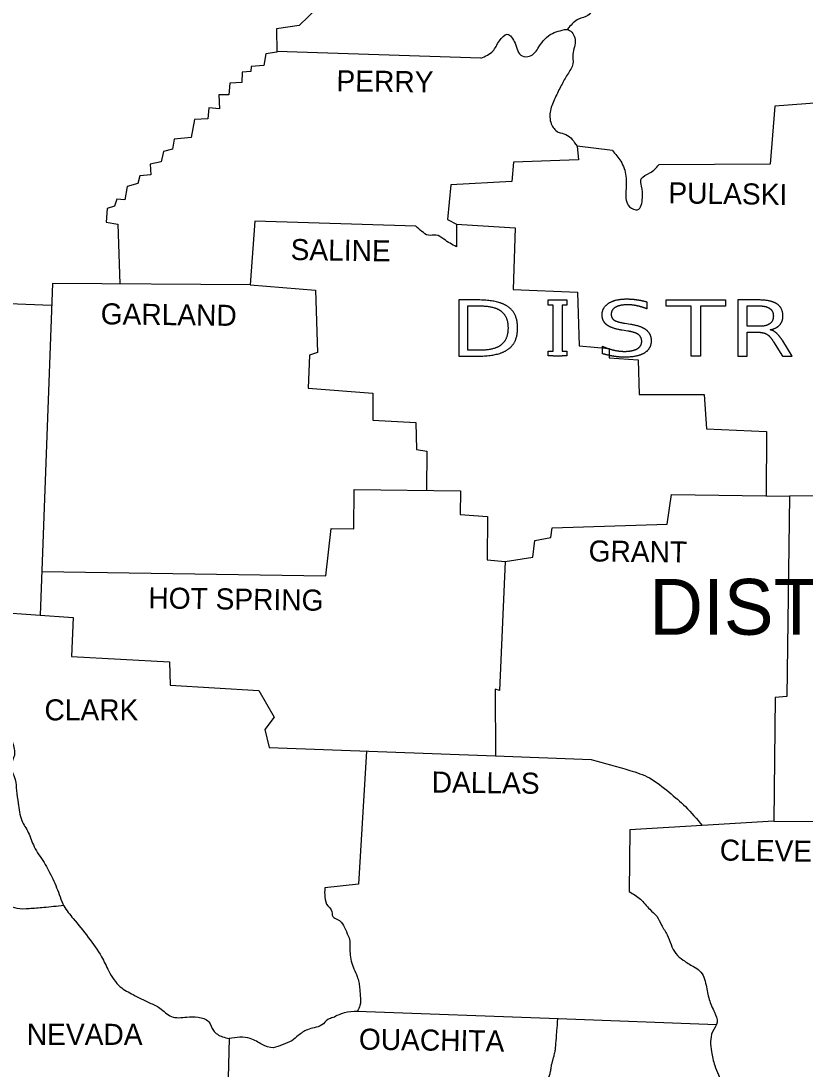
# Model space of a CAD drawing. Extents: x -0.96 to 2.36, y -0.12 to 0.92.
# Drawn here: x 1.1608 to 1.2333, y 0.624 to 0.7208 of the extents above; entities that cross this region are included whole.
import ezdxf

# ---------------------------------------------------------------- set-up
doc = ezdxf.new("R2010")
doc.units = 0
doc.layers.add('SHET_Annotations', color=7, linetype='Continuous')

msp = doc.modelspace()

# ---------------------------------------------------------------- linework, layer by layer
at = {"layer": 'SHET_Annotations'}
for p, q in [((1.211496, 0.720197), (1.211336, 0.720023)), ((1.218708, 0.694862), (1.218708, 0.694215)), ((1.216665, 0.692883), (1.217197, 0.692796)), ((1.216948, 0.692159), (1.216412, 0.692243)), ((1.230111, 0.692278), (1.230111, 0.692278)), ((1.214591, 0.690068), (1.214591, 0.690754))]:
    msp.add_line(p, q, dxfattribs=at)
for points in [[(1.233615, 0.817917), (1.233721, 0.806791), (1.232969, 0.806739), (1.233073, 0.79538), (1.229909, 0.794913), (1.230168, 0.791879), (1.231257, 0.790452), (1.23118, 0.786847), (1.224981, 0.786614), (1.224748, 0.781064), (1.219094, 0.780883), (1.218783, 0.774088), (1.21912, 0.773569), (1.219276, 0.76278), (1.229001, 0.762132), (1.228871, 0.738091), (1.236652, 0.737884), (1.236652, 0.713402), (1.230531, 0.712935), (1.23009, 0.707592), (1.219795, 0.707515)], [(1.18831, 0.72209), (1.186547, 0.720404), (1.184472, 0.720067), (1.184498, 0.717914), (1.183487, 0.717785), (1.183305, 0.716695), (1.182138, 0.716592), (1.182086, 0.716125), (1.181282, 0.716073), (1.181256, 0.715113), (1.180141, 0.715062), (1.180063, 0.713972), (1.17913, 0.713972), (1.179182, 0.712676), (1.178196, 0.712779), (1.178118, 0.711768), (1.176899, 0.71169), (1.176562, 0.71003), (1.175006, 0.709901), (1.174851, 0.708967), (1.174021, 0.70876), (1.173813, 0.7078), (1.172776, 0.707592), (1.172854, 0.706607), (1.171816, 0.706503), (1.171635, 0.705777), (1.170675, 0.705518), (1.170442, 0.704273), (1.16969, 0.704351), (1.169482, 0.703702), (1.168808, 0.703469), (1.16873, 0.702224), (1.169793, 0.702043), (1.169983, 0.696509)], [(1.203352, 0.71737), (1.184497, 0.717994)], [(1.215515, 0.708837), (1.212248, 0.709226), (1.212377, 0.707981), (1.206387, 0.707748), (1.206205, 0.705985), (1.200577, 0.705673), (1.200266, 0.702458), (1.201096, 0.702043), (1.201096, 0.699942)], [(1.197335, 0.701861), (1.182449, 0.702302), (1.182034, 0.696441), (1.163751, 0.696545), (1.162627, 0.665923)], [(1.201096, 0.702037), (1.206542, 0.701705), (1.206335, 0.696), (1.2123, 0.695766), (1.212429, 0.690787), (1.21523, 0.690554), (1.21523, 0.689698), (1.217901, 0.68949), (1.217979, 0.686301), (1.223996, 0.686301), (1.224203, 0.683137), (1.229753, 0.682877), (1.229727, 0.676943)], [(1.182034, 0.696441), (1.188077, 0.695922), (1.188259, 0.690165), (1.187506, 0.689931), (1.187403, 0.686871), (1.193368, 0.68643), (1.193368, 0.683915), (1.197335, 0.683707), (1.197413, 0.681217), (1.198347, 0.681062), (1.198319, 0.677447)], [(1.145519, 0.695248), (1.163677, 0.694537)], [(1.203115, 0.69503), (1.201329, 0.69503), (1.201329, 0.689845), (1.203115, 0.689845)], [(1.20325, 0.69039), (1.202165, 0.69039), (1.202165, 0.694484), (1.20325, 0.694484)], [(1.229087, 0.69503), (1.227122, 0.69503), (1.227122, 0.689845), (1.227959, 0.689845), (1.227959, 0.692051), (1.228939, 0.692051)], [(1.229087, 0.692596), (1.227959, 0.692596), (1.227959, 0.694484), (1.229087, 0.694484)], [(1.230407, 0.691173), (1.231235, 0.689845), (1.232128, 0.689845), (1.231256, 0.691247)], [(1.284163, 0.682177), (1.266891, 0.68267), (1.266787, 0.677042), (1.23188, 0.676912)], [(1.162775, 0.669939), (1.189037, 0.669547), (1.189529, 0.673904), (1.191604, 0.673878), (1.191656, 0.677535), (1.201485, 0.677405), (1.201433, 0.675201), (1.203975, 0.675019), (1.203949, 0.671025), (1.205609, 0.67087)], [(1.205609, 0.67087), (1.20815, 0.671259), (1.208332, 0.672815), (1.209836, 0.673074), (1.20994, 0.673982), (1.220573, 0.674319), (1.220987, 0.677068), (1.23188, 0.676912)], [(1.23188, 0.676912), (1.231646, 0.658395), (1.230557, 0.658317), (1.230453, 0.646881)], [(1.205609, 0.67087), (1.205064, 0.65894), (1.204675, 0.65907), (1.204701, 0.65291)], [(1.157578, 0.657721), (1.157449, 0.660237), (1.158201, 0.660288), (1.158668, 0.666201), (1.16567, 0.665709), (1.165514, 0.662104), (1.174565, 0.661611), (1.174643, 0.659433), (1.182838, 0.65894), (1.184239, 0.656476), (1.183383, 0.655361), (1.183798, 0.653675), (1.204701, 0.65291)], [(1.192778, 0.653346), (1.192045, 0.641071), (1.188933, 0.640708)], [(1.204701, 0.65291), (1.213544, 0.652586)], [(1.230453, 0.646881), (1.223815, 0.64648)], [(1.230453, 0.646881), (1.246686, 0.646802)], [(1.223815, 0.64648), (1.217123, 0.646077), (1.217071, 0.640371)], [(1.191933, 0.629337), (1.21051, 0.628649), (1.22514, 0.628079)], [(1.180089, 0.626807), (1.179493, 0.603778), (1.173346, 0.604219), (1.173294, 0.602533), (1.165185, 0.603001)]]:
    msp.add_lwpolyline(points, dxfattribs=at)
for points in [[(1.210034, 0.69454), (1.209572, 0.69454), (1.209572, 0.695058), (1.211306, 0.695058), (1.211306, 0.69454), (1.21087, 0.69454), (1.21087, 0.690296), (1.211306, 0.690296), (1.211306, 0.689859), (1.21087, 0.689859), (1.21087, 0.689845), (1.210034, 0.689845), (1.210034, 0.689859), (1.209589, 0.689859), (1.209589, 0.690296), (1.210034, 0.690296)], [(1.2205, 0.69503), (1.225958, 0.69503), (1.225958, 0.69447), (1.223649, 0.69447), (1.223649, 0.689845), (1.222809, 0.689845), (1.222809, 0.69447), (1.2205, 0.69447)]]:
    msp.add_lwpolyline(points, close=True, dxfattribs=at)
for points in [[(1.215567, 0.732775), (1.214945, 0.731711), (1.214711, 0.730337), (1.213959, 0.729455), (1.213493, 0.728495), (1.213467, 0.727147), (1.213674, 0.725954), (1.213907, 0.724839), (1.214115, 0.723775), (1.213856, 0.722453), (1.213259, 0.721312), (1.212377, 0.720975), (1.211496, 0.720197)], [(1.203352, 0.71737), (1.204467, 0.718018), (1.205064, 0.718978), (1.20579, 0.719574), (1.206516, 0.718744), (1.207165, 0.717577), (1.207865, 0.717551), (1.208721, 0.718407), (1.209265, 0.719133), (1.209965, 0.719652), (1.210692, 0.719911), (1.211444, 0.719989), (1.212066, 0.719107), (1.211859, 0.717733), (1.211859, 0.716851), (1.211366, 0.715865), (1.210795, 0.714854), (1.210225, 0.713713), (1.209784, 0.71252), (1.209862, 0.711301), (1.21051, 0.710549), (1.21121, 0.710316), (1.212248, 0.709226)], [(1.215515, 0.708837), (1.216293, 0.707852), (1.21676, 0.706477), (1.21676, 0.704921), (1.217097, 0.70365), (1.217849, 0.703365), (1.21829, 0.70448), (1.218213, 0.705544), (1.218187, 0.706218), (1.218991, 0.706763), (1.219795, 0.707515)], [(1.201096, 0.699942), (1.199929, 0.700642), (1.199203, 0.701031), (1.198503, 0.701005), (1.197906, 0.701368), (1.197335, 0.701861)], [(1.157578, 0.657721), (1.158279, 0.65728), (1.15916, 0.656865), (1.159627, 0.656191), (1.159783, 0.655128), (1.16012, 0.653986), (1.160198, 0.652819), (1.159938, 0.652171), (1.160301, 0.650719), (1.160431, 0.649707), (1.160587, 0.64854), (1.160924, 0.646932), (1.16152, 0.645843), (1.162065, 0.64452), (1.162973, 0.643068), (1.163777, 0.641538), (1.16414, 0.640734), (1.164814, 0.639048), (1.16567, 0.637881), (1.16707, 0.636144), (1.168289, 0.634354), (1.168963, 0.633032), (1.170027, 0.631579), (1.17122, 0.630853), (1.172724, 0.630101), (1.173684, 0.629608), (1.174747, 0.62883), (1.176173, 0.628778), (1.177211, 0.628778), (1.178196, 0.628338), (1.178637, 0.627534), (1.179467, 0.626963), (1.180089, 0.626807)], [(1.213544, 0.652586), (1.217123, 0.651575), (1.218939, 0.650874), (1.220754, 0.649552), (1.222258, 0.648229), (1.223815, 0.64648)], [(1.138889, 0.642596), (1.140799, 0.642446), (1.142407, 0.642264), (1.143626, 0.642135), (1.144897, 0.641694), (1.146064, 0.641279), (1.14679, 0.640942), (1.148009, 0.641019), (1.149072, 0.640812), (1.150239, 0.640397), (1.151121, 0.639619), (1.151691, 0.639022), (1.152729, 0.638789), (1.15361, 0.638945), (1.154648, 0.638841), (1.155815, 0.638504), (1.1568, 0.63853), (1.157578, 0.638711), (1.158486, 0.638919), (1.159601, 0.639048), (1.160457, 0.638841), (1.161598, 0.638815), (1.162947, 0.638919), (1.164777, 0.639118)], [(1.188933, 0.640708), (1.188933, 0.639852), (1.189218, 0.639048), (1.189529, 0.638685), (1.189685, 0.638063), (1.1901, 0.637804), (1.19067, 0.637233), (1.191008, 0.636481), (1.191215, 0.635962), (1.191241, 0.635314), (1.191267, 0.634691), (1.191371, 0.633939), (1.191915, 0.632539), (1.192071, 0.631994), (1.192149, 0.631527), (1.192201, 0.630749), (1.192175, 0.629842), (1.191933, 0.629337)], [(1.217071, 0.640371), (1.218109, 0.639671), (1.218965, 0.638737), (1.219613, 0.638089), (1.220054, 0.637285), (1.220573, 0.636377), (1.221377, 0.63464), (1.222051, 0.634043), (1.22301, 0.633447), (1.223581, 0.633058), (1.224177, 0.631735), (1.224463, 0.630412), (1.224955, 0.629219), (1.225189, 0.628312), (1.224774, 0.627404), (1.22467, 0.625589), (1.224981, 0.624318), (1.225319, 0.623436), (1.225552, 0.622373), (1.225396, 0.622061)], [(1.189684, 0.628753), (1.189218, 0.628545), (1.188648, 0.628052), (1.187947, 0.627793), (1.187325, 0.627611), (1.186469, 0.627067), (1.185873, 0.6266), (1.184991, 0.626211), (1.184161, 0.625952), (1.183149, 0.626237), (1.182605, 0.626548), (1.182034, 0.626807), (1.180089, 0.626807)], [(1.189684, 0.628753), (1.190748, 0.629193), (1.191933, 0.629337)]]:
    msp.add_spline(points, degree=3, dxfattribs=at)
for points, degree in [([(1.205875, 0.694404), (1.204997, 0.69503), (1.203115, 0.69503)], 2), ([(1.20325, 0.694484), (1.204605, 0.694484), (1.205237, 0.693993)], 2), ([(1.206753, 0.692443), (1.206753, 0.693778), (1.205875, 0.694404)], 2), ([(1.214565, 0.693652), (1.214565, 0.694334), (1.215167, 0.694729)], 2), ([(1.215167, 0.694729), (1.215768, 0.695124), (1.216826, 0.695124)], 2), ([(1.215803, 0.694359), (1.215406, 0.694131), (1.215406, 0.693708)], 2), ([(1.216926, 0.694586), (1.216199, 0.694586), (1.215803, 0.694359)], 2), ([(1.216826, 0.695124), (1.217284, 0.695124), (1.217756, 0.695058)], 2), ([(1.217789, 0.694491), (1.21734, 0.694586), (1.216926, 0.694586)], 2), ([(1.217756, 0.695058), (1.218229, 0.694991), (1.218708, 0.694862)], 2), ([(1.218708, 0.694215), (1.218238, 0.694397), (1.217789, 0.694491)], 2), ([(1.230736, 0.694659), (1.230193, 0.69503), (1.229087, 0.69503)], 2), ([(1.229087, 0.694484), (1.229732, 0.694484), (1.230063, 0.694247)], 2), ([(1.231278, 0.693544), (1.231278, 0.694289), (1.230736, 0.694659)], 2), ([(1.205237, 0.693993), (1.205868, 0.693502), (1.205868, 0.692443)], 2), ([(1.214999, 0.692729), (1.214565, 0.693061), (1.214565, 0.693652)], 2), ([(1.215406, 0.693708), (1.215406, 0.693352), (1.215672, 0.693173)], 2), ([(1.230063, 0.694247), (1.230394, 0.694009), (1.230394, 0.693544)], 2), ([(1.230394, 0.693544), (1.230394, 0.693079), (1.230063, 0.692838)], 2), ([(1.230997, 0.692738), (1.231278, 0.693058), (1.231278, 0.693544)], 2), ([(1.205868, 0.692443), (1.205868, 0.691376), (1.205237, 0.690883)], 2), ([(1.205873, 0.690472), (1.206753, 0.6911), (1.206753, 0.692443)], 2), ([(1.216412, 0.692243), (1.215432, 0.692397), (1.214999, 0.692729)], 2), ([(1.215672, 0.693173), (1.215938, 0.692995), (1.216665, 0.692883)], 2), ([(1.217197, 0.692796), (1.218177, 0.692649), (1.218639, 0.692273)], 2), ([(1.230063, 0.692838), (1.229732, 0.692596), (1.229087, 0.692596)], 2), ([(1.230111, 0.692278), (1.230716, 0.692418), (1.230997, 0.692738)], 2), ([(1.217926, 0.691829), (1.217628, 0.692051), (1.216948, 0.692159)], 2), ([(1.218225, 0.691215), (1.218225, 0.691607), (1.217926, 0.691829)], 2), ([(1.218639, 0.692273), (1.2191, 0.691897), (1.2191, 0.691268)], 2), ([(1.228939, 0.692051), (1.22947, 0.692051), (1.229777, 0.691878)], 2), ([(1.229777, 0.691878), (1.230085, 0.691705), (1.230407, 0.691173)], 2), ([(1.230721, 0.691934), (1.230455, 0.692184), (1.230111, 0.692278)], 2), ([(1.231256, 0.691247), (1.230986, 0.691684), (1.230721, 0.691934)], 2), ([(1.203115, 0.689845), (1.204993, 0.689845), (1.205873, 0.690472)], 2), ([(1.205237, 0.690883), (1.204605, 0.69039), (1.20325, 0.69039)], 2), ([(1.214591, 0.690754), (1.215097, 0.69053), (1.215613, 0.690406)], 2), ([(1.215613, 0.690406), (1.216129, 0.690282), (1.21663, 0.690282)], 2), ([(1.21663, 0.690282), (1.217393, 0.690282), (1.217809, 0.690523)], 2), ([(1.217809, 0.690523), (1.218225, 0.690764), (1.218225, 0.691215)], 2), ([(1.2191, 0.691268), (1.2191, 0.690516), (1.218473, 0.69013)], 2), ([(1.215652, 0.689827), (1.215136, 0.689911), (1.214591, 0.690068)], 2), ([(1.21663, 0.689743), (1.216169, 0.689743), (1.215652, 0.689827)], 2), ([(1.218473, 0.69013), (1.217846, 0.689743), (1.21663, 0.689743)], 2), ([(1.210448, 0.628651), (1.210373, 0.627717), (1.210299, 0.626782), (1.210225, 0.625848), (1.210206, 0.625609), (1.210149, 0.625374), (1.210084, 0.625143), (1.210052, 0.625027), (1.210015, 0.624912), (1.209982, 0.624796), (1.20995, 0.62468), (1.209916, 0.624564), (1.209888, 0.624447), (1.209835, 0.624231), (1.20982, 0.624007), (1.209778, 0.623788), (1.209757, 0.623679), (1.209735, 0.62357), (1.209706, 0.623462), (1.209691, 0.623408), (1.209672, 0.623356), (1.20965, 0.623304), (1.20964, 0.623278), (1.209628, 0.623252), (1.209616, 0.623227), (1.209604, 0.623201), (1.209591, 0.623176), (1.209576, 0.623151), (1.209534, 0.623076), (1.209485, 0.623007), (1.209428, 0.622943), (1.209371, 0.62288), (1.209312, 0.622821), (1.20925, 0.622764), (1.209187, 0.622708), (1.209122, 0.622654), (1.20906, 0.622597), (1.208998, 0.622541), (1.208935, 0.622485), (1.208876, 0.622425), (1.208755, 0.622299), (1.208634, 0.622174), (1.208513, 0.622049), (1.208392, 0.621923), (1.208271, 0.621798), (1.20815, 0.621672), (1.207911, 0.621425), (1.207704, 0.621148), (1.207502, 0.620869), (1.207445, 0.62079), (1.207389, 0.62071), (1.207339, 0.620627), (1.20729, 0.620544), (1.20724, 0.62046), (1.20719, 0.620377), (1.207141, 0.620293), (1.207091, 0.620209), (1.207041, 0.620126), (1.206992, 0.620042), (1.206936, 0.619962), (1.206879, 0.619883), (1.206703, 0.619638), (1.206498, 0.619422), (1.206283, 0.619209), (1.20605, 0.618978), (1.205811, 0.618755), (1.205531, 0.618586), (1.205267, 0.618428), (1.204998, 0.618286), (1.204727, 0.618145), (1.204452, 0.618003), (1.204178, 0.617862), (1.203897, 0.61773), (1.20382, 0.617695), (1.203741, 0.617665), (1.203659, 0.617645), (1.203577, 0.617626), (1.203494, 0.617608), (1.203411, 0.617591), (1.203327, 0.617574), (1.203243, 0.617559), (1.203159, 0.617542), (1.203075, 0.617524), (1.202993, 0.617499), (1.202911, 0.617471), (1.202781, 0.617427), (1.202659, 0.617368), (1.202541, 0.617293), (1.202482, 0.617256), (1.202429, 0.617214), (1.202379, 0.617167), (1.202353, 0.617142), (1.202329, 0.617117), (1.202305, 0.617091), (1.20228, 0.617063), (1.202258, 0.617035), (1.202237, 0.617004), (1.20218, 0.616922), (1.202143, 0.616834), (1.202114, 0.616737), (1.202084, 0.616642), (1.202073, 0.616544), (1.202082, 0.616449), (1.2021, 0.61626), (1.202133, 0.616069), (1.202211, 0.615889), (1.202269, 0.615757), (1.202327, 0.615632), (1.202392, 0.615507), (1.202458, 0.615381), (1.202525, 0.615255), (1.202591, 0.615128), (1.202658, 0.615002), (1.202723, 0.614875), (1.202789, 0.614748), (1.202853, 0.614621), (1.20291, 0.614491), (1.202963, 0.614359), (1.203059, 0.61412), (1.203142, 0.613877), (1.203223, 0.613633), (1.203247, 0.613559), (1.203269, 0.613485), (1.20329, 0.61341), (1.203312, 0.613334), (1.203328, 0.613258), (1.203342, 0.61318), (1.203356, 0.613104), (1.203364, 0.613027), (1.203367, 0.61295), (1.203369, 0.612913), (1.203367, 0.612875), (1.203365, 0.612837), (1.203364, 0.612799), (1.203359, 0.612762), (1.203352, 0.612725), (1.203333, 0.612624), (1.203289, 0.612533), (1.203223, 0.612448), (1.203155, 0.61236), (1.203079, 0.612289), (1.202989, 0.612232), (1.202758, 0.612087), (1.202527, 0.611948), (1.202289, 0.611817), (1.201997, 0.611657), (1.201699, 0.611512), (1.201407, 0.611351), (1.201144, 0.611205), (1.200897, 0.61104), (1.200655, 0.610858), (1.200528, 0.610762), (1.200418, 0.61065), (1.200319, 0.610524), (1.20027, 0.610461), (1.200228, 0.610395), (1.200189, 0.610325), (1.200149, 0.610254), (1.200115, 0.610183), (1.200085, 0.610106), (1.200017, 0.609932), (1.199973, 0.609754), (1.199963, 0.609573), (1.199953, 0.609397), (1.199964, 0.609215), (1.200007, 0.609043), (1.200032, 0.60894), (1.200057, 0.608838), (1.200087, 0.608738), (1.200116, 0.608636), (1.200146, 0.608535), (1.200175, 0.608433), (1.200205, 0.608332), (1.200234, 0.60823), (1.200264, 0.608129), (1.200293, 0.608028), (1.20032, 0.607926), (1.200344, 0.607824), (1.200402, 0.607574), (1.200445, 0.607322), (1.200499, 0.607072), (1.200523, 0.606964), (1.200549, 0.606858), (1.200575, 0.606751), (1.200601, 0.606642), (1.200637, 0.606537), (1.200677, 0.606432), (1.200715, 0.606331), (1.20077, 0.60624), (1.200839, 0.606155), (1.200873, 0.606112), (1.200911, 0.606076), (1.200954, 0.606043), (1.200975, 0.606026), (1.200998, 0.606011), (1.201021, 0.605996), (1.201045, 0.605981), (1.201069, 0.605968), (1.201096, 0.605956), (1.201132, 0.605941), (1.201169, 0.605931), (1.201206, 0.605932), (1.201243, 0.605932), (1.20128, 0.605937), (1.201316, 0.605944), (1.201353, 0.605951), (1.201389, 0.605963), (1.201427, 0.605969), (1.201463, 0.605975), (1.2015, 0.605979), (1.201537, 0.605982), (1.201571, 0.605985), (1.201606, 0.605984), (1.201641, 0.605989), (1.201675, 0.605994), (1.20171, 0.606), (1.201744, 0.606006), (1.201814, 0.606017), (1.201883, 0.606029), (1.201952, 0.606041), (1.20202, 0.606052), (1.202091, 0.606047), (1.20216, 0.606034), (1.202196, 0.606026), (1.20223, 0.606014), (1.202263, 0.605997), (1.202281, 0.605989), (1.202298, 0.605979), (1.202315, 0.605968), (1.202333, 0.605957), (1.202351, 0.605946), (1.202367, 0.60593), (1.202399, 0.6059), (1.202419, 0.60586), (1.202429, 0.605818), (1.202438, 0.605778), (1.202436, 0.605737), (1.202445, 0.605697), (1.20246, 0.605628), (1.202478, 0.605559), (1.202496, 0.60549), (1.202552, 0.605286), (1.202615, 0.605089), (1.202704, 0.604893), (1.202732, 0.604831), (1.202779, 0.604773), (1.202839, 0.604743), (1.202906, 0.60471), (1.202973, 0.604678), (1.20304, 0.604646), (1.203107, 0.604613), (1.203175, 0.604581), (1.203242, 0.604548), (1.203302, 0.604519), (1.203349, 0.604463), (1.203378, 0.6044), (1.203395, 0.604363), (1.203407, 0.604326), (1.203413, 0.604287), (1.20342, 0.604247), (1.203426, 0.604208), (1.203433, 0.604168), (1.203439, 0.604128), (1.203444, 0.604088), (1.203451, 0.604049), (1.203457, 0.604009), (1.203469, 0.603971), (1.203482, 0.603933), (1.203533, 0.60378), (1.203597, 0.603633), (1.203662, 0.603485), (1.203728, 0.603333), (1.203804, 0.603192), (1.203897, 0.603052), (1.204063, 0.602801), (1.204271, 0.60257), (1.204545, 0.602455), (1.204716, 0.602384), (1.204889, 0.602327), (1.205064, 0.602274), (1.205409, 0.602168), (1.205754, 0.602062), (1.206101, 0.601962), (1.206281, 0.601911), (1.206465, 0.60188), (1.206646, 0.601833), (1.206674, 0.601825), (1.2067, 0.601815), (1.206725, 0.601797), (1.206801, 0.60174), (1.206856, 0.601664), (1.206873, 0.601577), (1.206902, 0.60143), (1.206926, 0.601284), (1.206953, 0.601137), (1.20698, 0.600997), (1.207006, 0.600856), (1.207035, 0.600715), (1.207046, 0.60066), (1.207077, 0.600614), (1.207124, 0.600573), (1.207168, 0.600534), (1.207216, 0.600514), (1.207268, 0.60051), (1.207389, 0.600501), (1.207511, 0.600501), (1.207631, 0.600514), (1.207753, 0.600528), (1.207874, 0.600538), (1.207994, 0.600562), (1.208081, 0.600579), (1.208167, 0.600599), (1.208254, 0.600617), (1.20834, 0.600634), (1.208427, 0.600651), (1.208513, 0.600666), (1.208668, 0.600693), (1.208829, 0.600681), (1.208984, 0.600649), (1.209065, 0.600633), (1.209142, 0.600606), (1.209217, 0.600571), (1.209257, 0.600552), (1.209295, 0.600532), (1.209332, 0.60051), (1.209372, 0.600486), (1.20941, 0.600462), (1.209447, 0.600432), (1.209539, 0.600359), (1.209621, 0.600275), (1.20968, 0.600174), (1.209735, 0.60008), (1.209787, 0.599985), (1.209836, 0.599888), (1.209875, 0.599811), (1.209916, 0.599735), (1.209951, 0.599656), (1.209986, 0.599578), (1.21002, 0.599499), (1.210054, 0.599421), (1.210089, 0.599343), (1.210124, 0.599264), (1.210159, 0.599186), (1.210194, 0.599107), (1.210236, 0.599031), (1.210277, 0.598954), (1.210363, 0.59879), (1.210438, 0.598615), (1.210562, 0.598476)], 3)]:
    msp.add_open_spline(points, degree=degree, dxfattribs=at)

# ---------------------------------------------------------------- texts
for s, rotation, p in [('PERRY', 359.29917, (1.189997, 0.714313)), ('PULASKI', 359.18542, (1.22068, 0.703963)), ('SALINE', 359.1885, (1.185759, 0.698725)), ('GARLAND', 359.2717, (1.168204, 0.692786)), ('GRANT', 359.31386, (1.213309, 0.670877)), ('HOT SPRING', 359.19559, (1.17261, 0.666541)), ('DALLAS', 359.28024, (1.198801, 0.649528)), ('CLEVELAND', 359.24116, (1.225433, 0.643244)), ('OUACHITA', 359.20269, (1.192072, 0.625773))]:
    msp.add_text(s, height=0.0019451, rotation=rotation, dxfattribs=at).set_placement(p)
for s, height, p in [('DISTRICT 2', 0.0051569, (1.218916, 0.664102)), ('CLARK', 0.0019451, (1.163018, 0.656191)), ('NEVADA', 0.0019451, (1.161386, 0.626211))]:
    msp.add_text(s, height=height, dxfattribs=at).set_placement(p)

doc.saveas('drawing.dxf')
